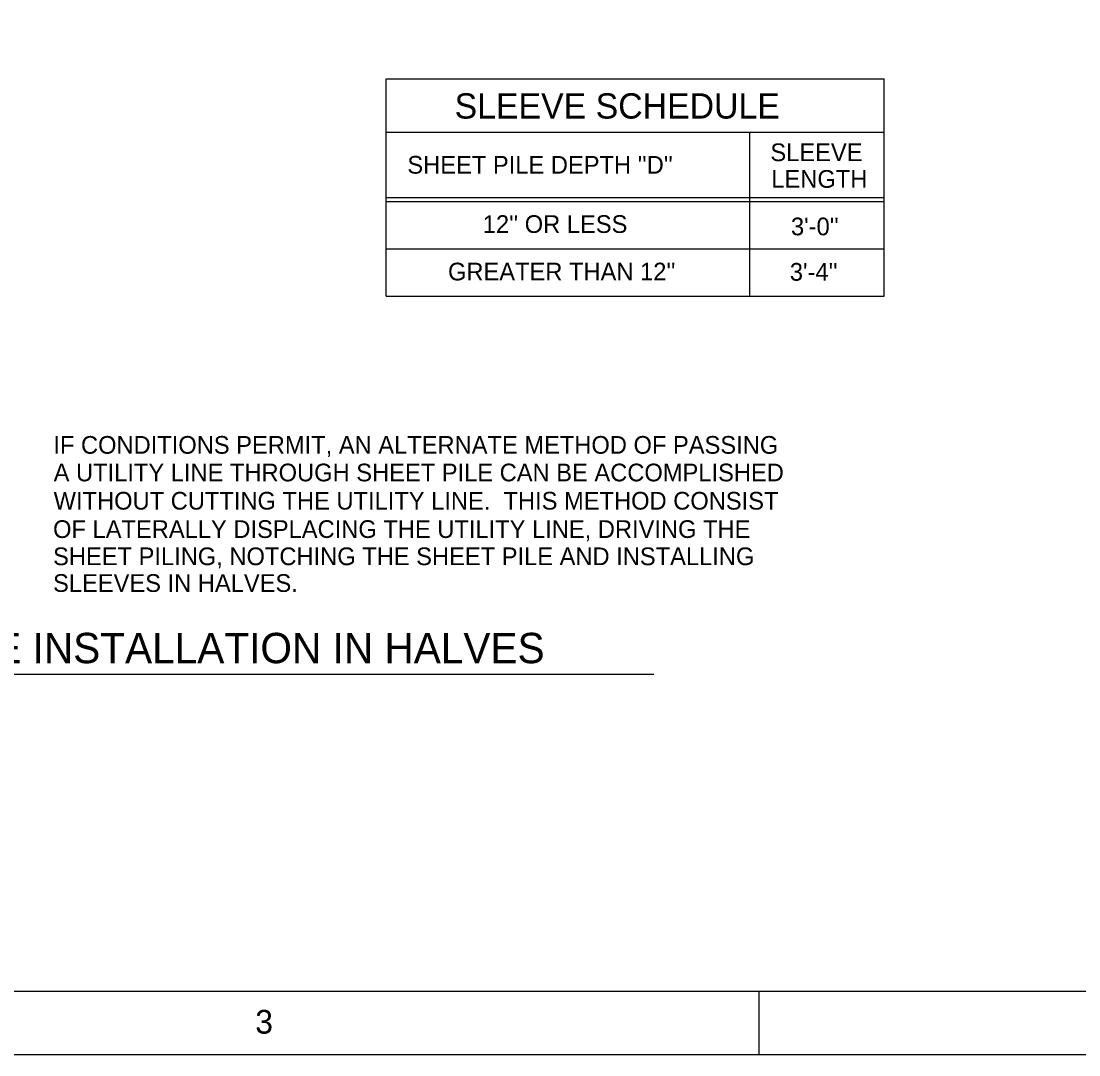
# Model space of a CAD drawing. Extents: x 22422.9 to 22498.9, y 22369.6 to 22415.
# Drawn here: x 22465.87 to 22477.02, y 22369.62 to 22380.52 of the extents above; entities that cross this region are included whole.
import ezdxf

# ---------------------------------------------------------------- set-up
doc = ezdxf.new("R2010")
doc.units = 0
for name, color, linetype in [('Level 1', 7, 'Continuous'), ('Level 10', 7, 'Continuous'), ('Level 2', 7, 'Continuous'), ('Level 3', 7, 'Continuous'), ('Level 4', 7, 'Continuous'), ('Level 7', 7, 'Continuous'), ('Level 9', 7, 'Continuous')]:
    doc.layers.add(name, color=color, linetype=linetype)

msp = doc.modelspace()

# ---------------------------------------------------------------- linework, layer by layer
at = {"layer": 'Level 1'}
msp.add_lwpolyline([(22440.26, 22414.965), (22498.927, 22414.965), (22498.927, 22369.621), (22440.26, 22369.621)], close=True, dxfattribs=at)
at = {"layer": 'Level 10'}
for p, q in [((22464.137, 22373.635), (22472.537, 22373.635)), ((22473.647, 22369.621), (22473.647, 22370.293))]:
    msp.add_line(p, q, dxfattribs=at)
at = {"layer": 'Level 2'}
for p, q in [((22469.715, 22378.663), (22474.965, 22378.663)), ((22469.715, 22378.622), (22474.965, 22378.622)), ((22469.715, 22378.122), (22474.965, 22378.122))]:
    msp.add_line(p, q, dxfattribs=at)
at = {"layer": 'Level 7'}
for p, q in [((22469.715, 22379.914), (22474.965, 22379.914)), ((22469.715, 22377.622), (22469.715, 22379.914)), ((22474.965, 22377.622), (22474.965, 22379.914)), ((22469.715, 22379.352), (22474.965, 22379.352)), ((22473.549, 22377.622), (22473.549, 22379.352)), ((22469.715, 22377.622), (22474.965, 22377.622))]:
    msp.add_line(p, q, dxfattribs=at)
at = {"layer": 'Level 9'}
msp.add_line((22442.26, 22370.293), (22494.591, 22370.293), dxfattribs=at)

# ---------------------------------------------------------------- texts
at = {"layer": 'Level 1'}
msp.add_text('3', height=0.25, dxfattribs=at).set_placement((22468.335, 22369.845))
at = {"layer": 'Level 3'}
msp.add_text('SLEEVE INSTALLATION IN HALVES', height=0.32, dxfattribs=at).set_placement((22464.203, 22373.752))
at = {"layer": 'Level 4'}
for s, height, p in [('SLEEVE SCHEDULE', 0.2667, (22470.436, 22379.496)), ('SLEEVE', 0.1867, (22473.765, 22379.047)), ("SHEET PILE DEPTH ''D''", 0.1867, (22469.938, 22378.915)), ('LENGTH', 0.1867, (22473.775, 22378.766)), ("12'' OR LESS", 0.1867, (22470.733, 22378.29)), ("3'-0''", 0.1867, (22473.982, 22378.265)), ("GREATER THAN 12''", 0.1867, (22470.366, 22377.789)), ("3'-4''", 0.1867, (22473.97, 22377.786)), ('IF CONDITIONS PERMIT, AN ALTERNATE METHOD OF PASSING', 0.18667, (22466.206, 22375.961)), ('A UTILITY LINE THROUGH SHEET PILE CAN BE ACCOMPLISHED', 0.18667, (22466.209, 22375.67)), ('WITHOUT CUTTING THE UTILITY LINE.  THIS METHOD CONSIST', 0.18667, (22466.209, 22375.372)), ('OF LATERALLY DISPLACING THE UTILITY LINE, DRIVING THE', 0.18667, (22466.203, 22375.073)), ('SHEET PILING, NOTCHING THE SHEET PILE AND INSTALLING', 0.18667, (22466.203, 22374.786)), ('SLEEVES IN HALVES.', 0.18667, (22466.203, 22374.504))]:
    msp.add_text(s, height=height, dxfattribs=at).set_placement(p)

doc.saveas('drawing.dxf')
